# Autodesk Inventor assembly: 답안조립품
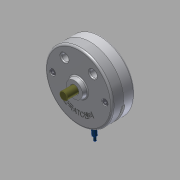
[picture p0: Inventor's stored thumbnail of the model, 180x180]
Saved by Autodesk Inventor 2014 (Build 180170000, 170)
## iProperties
Created: 2015-06
Part Number: 답안조립품
Document SubType Name: Assembly
Designer: MYHOME
Author: MYHOME
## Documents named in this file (10)
- C:\Documents and Settings\MYHOME\바탕 화면\450631V1033\답안조립품.iam
- C:\Documents and Settings\MYHOME\바탕 화면\450631V1033\덮개.ipt
- C:\Documents and Settings\MYHOME\바탕 화면\450631V1033\본체.ipt
- C:\Documents and Settings\MYHOME\바탕 화면\450631V1033\축.ipt
- C:\Documents and Settings\MYHOME\바탕 화면\450631V1033\베어링62_22.ipt
- C:\Documents and Settings\MYHOME\바탕 화면\450631V1033\멈춤링.ipt
- C:\Documents and Settings\MYHOME\바탕 화면\450631V1033\슬라이더2.ipt
- C:\Documents and Settings\MYHOME\바탕 화면\450631V1033\슬라이더.ipt
- C:\Documents and Settings\MYHOME\바탕 화면\450631V1033\평행핀.ipt
- C:\Documents and Settings\MYHOME\바탕 화면\450631V1033\M10x35.ipt
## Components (7 placed, 4 different names)
1. KS B 2023 62/22 - 22 x 50 x 14:1
2. KS B 2023 62/22 - 22 x 50 x 14:2
3. KS B 1336 22 x 1.2:1
4. KS B 1336 22 x 1.2:2
5. KS B 1320 B B 5 x  20:1
6. KS B 1003 - 미터 M 10 x 35:1
7. KS B 1003 - 미터 M 10 x 35:2
